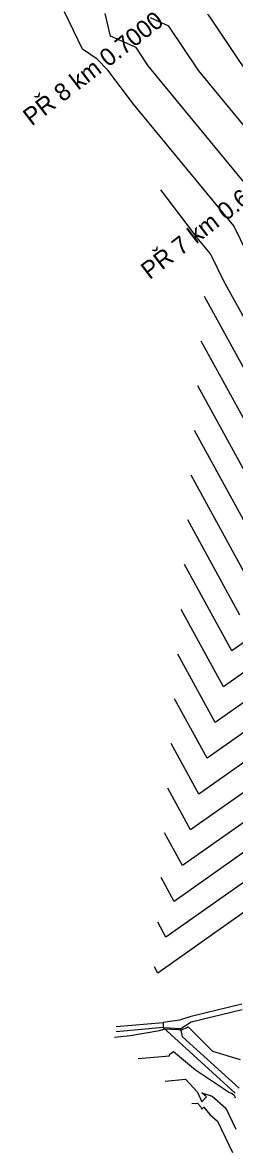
# Model space of a CAD drawing. Extents: x -549238 to -546764, y -1036895 to -1033794.
# Drawn here: x -548511 to -548402, y -1035558 to -1034976 of the extents above; entities that cross this region are included whole.
import ezdxf

# ---------------------------------------------------------------- set-up
doc = ezdxf.new("R2010")
doc.units = 0
for name, color, linetype in [('hlavni_vrst', 7, 'Continuous'), ('hrana_L', 7, 'Continuous'), ('norm_vrst', 7, 'Continuous'), ('x_popis_pricne_rezy_C12', 7, 'Continuous')]:
    doc.layers.add(name, color=color, linetype=linetype)

msp = doc.modelspace()

# ---------------------------------------------------------------- linework, layer by layer
at = {"layer": 'hlavni_vrst'}
for p, q in [((-548465.78, -1034982.48), (-548468.66, -1034970.86)), ((-548452.63, -1034988.35), (-548465.78, -1034982.48)), ((-548446.34, -1034997.78), (-548452.63, -1034988.35)), ((-548390, -1035066.03), (-548446.34, -1034997.78)), ((-548386.12, -1035225.87), (-548420.65, -1035162.96)), ((-548407.38, -1035318.19), (-548429.29, -1035278.27)), ((-548381.81, -1035300.17), (-548407.38, -1035318.19)), ((-548388.12, -1035381.95), (-548428.65, -1035410.51)), ((-548428.65, -1035410.51), (-548437.94, -1035393.59)), ((-548423.7, -1035533.31), (-548420.92, -1035533.06)), ((-548420.92, -1035533.06), (-548419.25, -1035534.82)), ((-548419.25, -1035534.82), (-548418.68, -1035536.12)), ((-548418.68, -1035536.12), (-548417.64, -1035535.08)), ((-548417.64, -1035535.08), (-548414.39, -1035538.86)), ((-548414.39, -1035538.86), (-548410.46, -1035542.31)), ((-548410.46, -1035542.31), (-548402.83, -1035558.47))]:
    msp.add_line(p, q, dxfattribs=at)
at = {"layer": 'hrana_L'}
for p, q in [((-548397.94, -1035481.98), (-548424.88, -1035488.54)), ((-548424.09, -1035491.03), (-548397.82, -1035484.75)), ((-548462.87, -1035493.45), (-548438.55, -1035491.49)), ((-548438.55, -1035491.49), (-548438.59, -1035494.02)), ((-548430.1, -1035490.31), (-548438.55, -1035491.49)), ((-548424.88, -1035488.54), (-548430.1, -1035490.31)), ((-548429.42, -1035494.49), (-548424.09, -1035491.03)), ((-548438.59, -1035494.02), (-548462.82, -1035496.27)), ((-548438.59, -1035494.02), (-548429.42, -1035494.49)), ((-548434.64, -1035497.68), (-548438.59, -1035494.02)), ((-548428.68, -1035498.83), (-548429.42, -1035494.49)), ((-548434.64, -1035497.68), (-548401.33, -1035527.85)), ((-548428.68, -1035498.83), (-548399.35, -1035525.24))]:
    msp.add_line(p, q, dxfattribs=at)
at = {"layer": 'norm_vrst'}
for p, q in [((-548394.04, -1035003.04), (-548418.56, -1034966.31)), ((-548480.23, -1034989.31), (-548489.69, -1034970.04)), ((-548435.59, -1034977.33), (-548445.09, -1034973.09)), ((-548420.19, -1035000.41), (-548435.59, -1034977.33)), ((-548472.73, -1034994.46), (-548480.23, -1034989.31)), ((-548467.28, -1035000.09), (-548472.73, -1034994.46)), ((-548453.9, -1035017.66), (-548467.28, -1035000.09)), ((-548377.94, -1035051.6), (-548420.19, -1035000.41)), ((-548402.06, -1035080.46), (-548453.9, -1035017.66)), ((-548420.09, -1035087.67), (-548439.72, -1035061.88)), ((-548395.09, -1035094.47), (-548402.06, -1035080.46)), ((-548414.12, -1035094.89), (-548420.09, -1035087.67)), ((-548413.32, -1035096.51), (-548414.12, -1035094.89)), ((-548407.15, -1035108.92), (-548413.32, -1035096.51)), ((-548373.36, -1035170.48), (-548407.15, -1035108.92)), ((-548377.61, -1035188.94), (-548417.19, -1035116.83)), ((-548381.87, -1035207.4), (-548418.92, -1035139.9)), ((-548390.37, -1035244.33), (-548422.38, -1035186.02)), ((-548394.62, -1035262.8), (-548424.11, -1035209.09)), ((-548398.88, -1035281.26), (-548425.84, -1035232.15)), ((-548403.13, -1035299.73), (-548427.57, -1035255.21)), ((-548380.55, -1035283.81), (-548403.13, -1035299.73)), ((-548411.64, -1035336.65), (-548431.02, -1035301.34)), ((-548383.07, -1035316.52), (-548411.64, -1035336.65)), ((-548415.89, -1035355.12), (-548432.75, -1035324.4)), ((-548384.33, -1035332.88), (-548415.89, -1035355.12)), ((-548420.14, -1035373.58), (-548434.48, -1035347.46)), ((-548385.59, -1035349.23), (-548420.14, -1035373.58)), ((-548386.85, -1035365.59), (-548424.4, -1035392.05)), ((-548424.4, -1035392.05), (-548436.21, -1035370.53)), ((-548389.38, -1035398.3), (-548432.9, -1035428.98)), ((-548390.64, -1035414.66), (-548437.15, -1035447.44)), ((-548432.9, -1035428.98), (-548439.67, -1035416.65)), ((-548391.9, -1035431.02), (-548441.41, -1035465.9)), ((-548437.15, -1035447.44), (-548441.4, -1035439.71)), ((-548441.41, -1035465.9), (-548443.12, -1035462.78)), ((-548455.6, -1035498.21), (-548440.56, -1035495.63)), ((-548440.56, -1035495.63), (-548437.77, -1035494.78)), ((-548437.77, -1035494.78), (-548430.46, -1035495.13)), ((-548430.46, -1035495.13), (-548429.27, -1035495.38)), ((-548429.27, -1035495.38), (-548425.65, -1035493.68)), ((-548425.65, -1035493.68), (-548413.16, -1035506.15)), ((-548463.69, -1035499.07), (-548455.6, -1035498.21)), ((-548451.5, -1035510.04), (-548435.39, -1035508.57)), ((-548435.39, -1035508.57), (-548435.23, -1035507.85)), ((-548435.23, -1035507.85), (-548433.28, -1035506.45)), ((-548433.28, -1035506.45), (-548421.87, -1035515.8)), ((-548413.16, -1035506.15), (-548398.79, -1035510.52)), ((-548421.87, -1035515.8), (-548404.25, -1035527.62)), ((-548437.6, -1035521.68), (-548427.12, -1035520.72)), ((-548427.12, -1035520.72), (-548420.8, -1035527.37)), ((-548420.8, -1035527.37), (-548418.64, -1035532.3)), ((-548418.66, -1035527.72), (-548413.23, -1035529.43)), ((-548416.14, -1035529.79), (-548418.66, -1035527.72)), ((-548418.64, -1035532.3), (-548416.14, -1035529.79)), ((-548413.23, -1035529.43), (-548406.21, -1035535.58)), ((-548404.25, -1035527.62), (-548402.88, -1035528.06)), ((-548402.88, -1035528.06), (-548401.97, -1035528.86)), ((-548401.97, -1035528.86), (-548401.3, -1035530.27)), ((-548406.21, -1035535.58), (-548401.1, -1035546.42))]:
    msp.add_line(p, q, dxfattribs=at)

# ---------------------------------------------------------------- texts
at = {"layer": 'x_popis_pricne_rezy_C12'}
for s, p in [('PŘ 8 km 0.7000', (-548506.57, -1035029.16)), ('PŘ 7 km 0.6000', (-548445.64, -1035108.45))]:
    msp.add_text(s, height=9.0627, rotation=37.53642, dxfattribs=at).set_placement(p)

doc.saveas('drawing.dxf')
